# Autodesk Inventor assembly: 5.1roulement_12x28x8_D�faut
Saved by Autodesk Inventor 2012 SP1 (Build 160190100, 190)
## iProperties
Created: 2011-01
Part Number: 5.1roulement_12x28x8_D�faut
Document SubType Name: Assembly
Designer: eric
Mass: 2.73783 g
Surface Area: 33.63 cm^2
Volume: 2.73783 cm^3
Density: 1 g/cm^3
Author: eric
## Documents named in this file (4)
- D:\Cours\Inventor salle SI\chariot_de_golf_2008\chariot_de_golf_trolem\5.1roulement_12x28x8_Defaut.iam
- D:\Cours\Inventor salle SI\chariot_de_golf_2008\chariot_de_golf_trolem\Roulement_r1rb_Bext27_Defaut.ipt
- D:\Cours\Inventor salle SI\chariot_de_golf_2008\chariot_de_golf_trolem\Roulement_r1rb_Eroul27_Defaut.ipt
- D:\Cours\Inventor salle SI\chariot_de_golf_2008\chariot_de_golf_trolem\Roulement_r1rb_Bint27_Defaut.ipt
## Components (12 placed, 3 different names)
1. Roulement_r1rb_Bext27_Defaut:1
2. Roulement_r1rb_Eroul27_Defaut:1
3. Roulement_r1rb_Eroul27_Defaut:2
4. Roulement_r1rb_Eroul27_Defaut:3
5. Roulement_r1rb_Eroul27_Defaut:4
6. Roulement_r1rb_Eroul27_Defaut:5
7. Roulement_r1rb_Eroul27_Defaut:6
8. Roulement_r1rb_Eroul27_Defaut:7
9. Roulement_r1rb_Eroul27_Defaut:8
10. Roulement_r1rb_Eroul27_Defaut:9
11. Roulement_r1rb_Eroul27_Defaut:10
12. Roulement_r1rb_Bint27_Defaut:1
